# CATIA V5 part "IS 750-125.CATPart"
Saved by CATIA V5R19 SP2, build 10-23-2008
Part number: IS 750-125
Bounding box of the stored display mesh (mm): x -24.865 to 24.865, y -24.997 to 24.997, z 0 to 345
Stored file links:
  C:\Users\Bora\Desktop\3D Katı model\IS serisi\IS 750\IS 750-125.CATPart
  C:\Program Files\Dassault Systemes\B19\intel_a\reffiles\standard\MetricThickPitch.txt
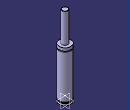
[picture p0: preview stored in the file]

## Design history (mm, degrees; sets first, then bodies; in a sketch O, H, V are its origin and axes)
Body1 (main body)
  Sketch1 on yz-plane, origin (0, 0, 0), H (0, 1, 0), V (0, 0, 1)
    point P1 (25, 204.5)
    point P4 (25, 200.5)
    point P7 (12.5, 344)
    point P9 (12.5, 344)
    point P13 (25, 204.5)
    point P14 (25, 200.5)
    line L1 (25, 204.5) -> (25, 217)
    line L2 (25, 13) -> (25, 200.5)
    line L3 (21.5, 13) -> (21.5, 8)
    arc A1 centre (11.5, 344) radius 1 from (12.5, 344) to (11.5, 345) ccw
    line L4 (12.5, 344) -> (12.5, 217)
    line L5 (25, 0) -> (25, 8)
    arc A2 centre (25, 202.5) radius 2 from (25, 204.5) to (25, 200.5) ccw
    line L6 (11.5, 345) -> (0, 345)
    point P15 (0, 345)
    line L7 (12.5, 217) -> (25, 217)
    line L8 (0, 0) -> (25, 0)
    line L9 (21.5, 13) -> (25, 13)
    line L10 (21.5, 8) -> (25, 8)
    coincidence: P15 V, P1 P13, P4 P14, P7 P9
    tangency: L6 A1
    horizontal: L7 H, L8 H, L9 H, L10 H
  Shaft1: profile Sketch1, axis Sketch1.V, angle 360
  Sketch2 on face of Shaft1 from Sketch1.L8, origin (0, 0, 0), H (1, 0, 0), V (0, -1, 0)
    point P1 (10, 0)
    distance V P1 = 10
  Hole1: placed by Sketch2, at (10, 0, 0) direction (0, 0, 1), diameter 6.647, depth 13, threaded "M8", thread diameter 8, thread depth 13, pitch 1.25
  Sketch3 on face of Shaft1 from Sketch1.L8, origin (0, 0, 0), H (1, 0, 0), V (0, -1, 0)
    point P1 (-10, 0)
    distance P1 V = 10
  Hole2: placed by Sketch3, at (-10, 0, 0) direction (0, 0, 1), diameter 6.647, depth 13, threaded "M8", thread diameter 8, thread depth 13, pitch 1.25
